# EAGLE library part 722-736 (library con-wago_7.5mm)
Serie 722, Federleiste mit geraden Einlötstiften / Series 722, Female connector with straight solder pins Polzahl / Pole No.: 6 Rastermaß / Pitch: 7.5 mm Bemessungsspannung / Rated Voltage: 630 V Nennstrom / Nominal Current: 12 A Lötstiftlänge: / Solder Pin Length: 5 mm Farbe / Color: lichtgrau / light gray Stand: 01.01.2012. Die jeweils aktuellen Daten zu diesem Artikel finden Sie in unserem Produktkatalog, den Sie unter www.wago.com einsehen können. As of: 01/01/2012. Please find the newest data for this article in our product catalogue, which can be viewed under www.wago.com.
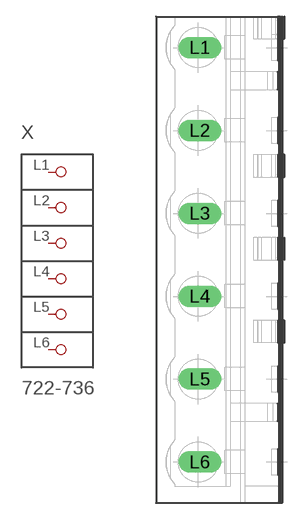
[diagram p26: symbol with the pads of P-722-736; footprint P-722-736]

Designator prefix X

## 722-736  [P-722-736]
L1  P1
L2  P2
L3  P3
L4  P4
L5  P5
L6  P6

## Footprint P-722-736 (pad centres in mm)
drill 1.3 long: L1 -1.983,19.2; L2 -1.983,11.7; L3 -1.983,4.2; L4 -1.983,-3.3; L5 -1.983,-10.8; L6 -1.983,-18.3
